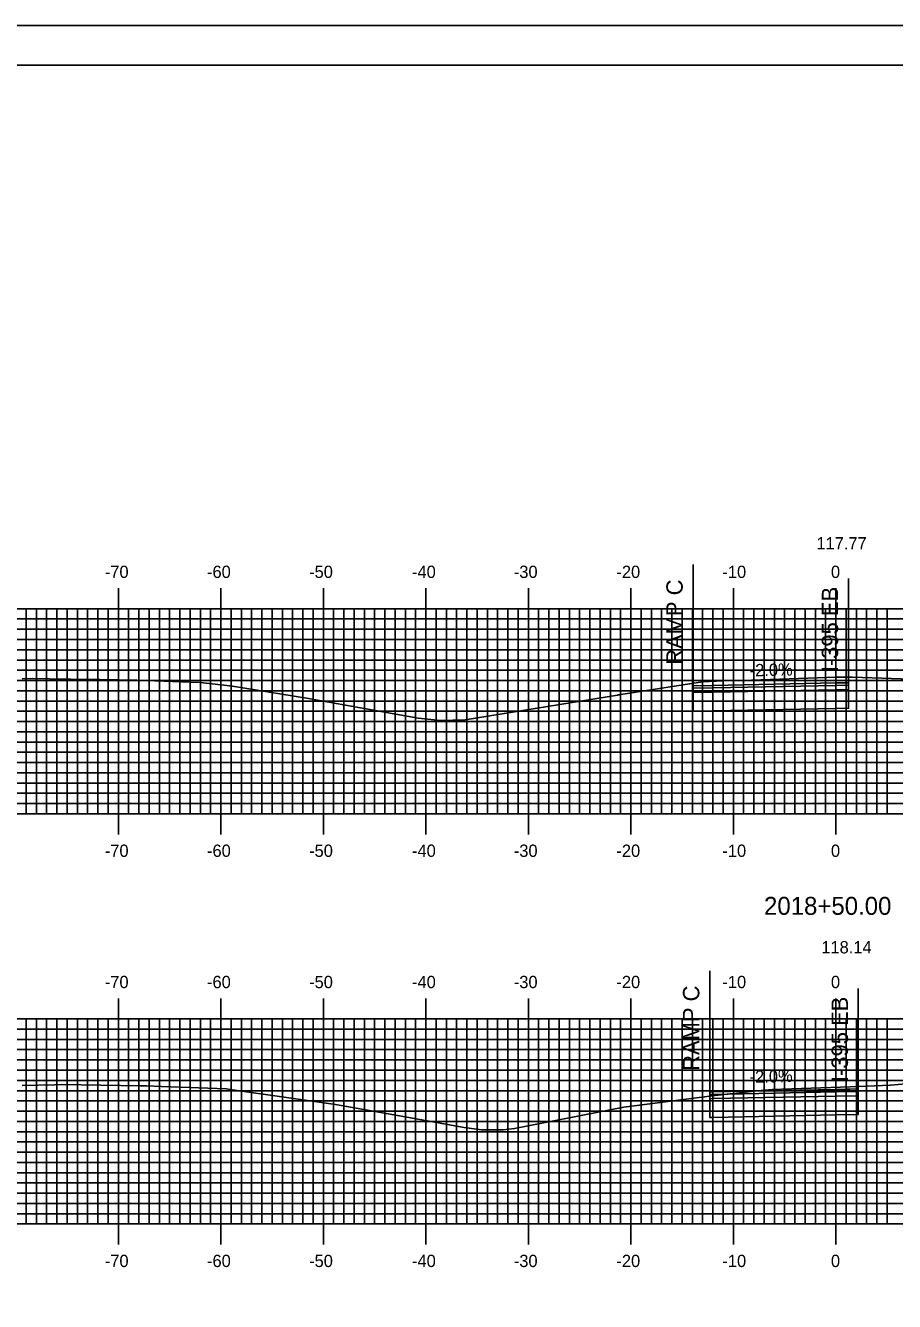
# Model space of a CAD drawing. Extents: x 855074 to 855418, y 366605 to 366825.
# Drawn here: x 855161 to 855245.8, y 366700.5 to 366824.9 of the extents above; entities that cross this region are included whole.
import ezdxf

# ---------------------------------------------------------------- set-up
doc = ezdxf.new("R2010")
doc.units = 0
for name, color, linetype in [('ANNOTATION', 7, 'Continuous'), ('BORDER', 7, 'Continuous'), ('D_Roadway_Centerline', 7, 'Continuous'), ('D_Roadway_Centerline_Text', 7, 'Continuous'), ('D_Roadway_Edge_Shoulder', 7, 'Continuous'), ('D_Roadway_Edge_TW', 7, 'Continuous'), ('D_Roadway_Pavement', 7, 'Continuous'), ('D_Roadway_SubGrade', 7, 'Continuous'), ('H_V ANNOTATION', 7, 'Continuous'), ('M_Roadway_Centerline', 7, 'Continuous'), ('MAJOR', 7, 'Continuous'), ('MINOR', 7, 'Continuous'), ('PLOT BOUNDARY', 7, 'Continuous'), ('S_Roadway_Centerline', 7, 'Continuous')]:
    doc.layers.add(name, color=color, linetype=linetype)

msp = doc.modelspace()

# ---------------------------------------------------------------- linework, layer by layer
at = {"layer": 'BORDER'}
msp.add_lwpolyline([(855090.47, 366611.06), (855410.47, 366611.06), (855410.47, 366821.06), (855090.47, 366821.06)], close=True, dxfattribs=at)
at = {"layer": 'D_Roadway_Centerline'}
for points in [[(855226.14, 366760.55), (855228.07, 366760.59), (855240.07, 366760.83), (855240.07, 366760.83), (855240.63, 366760.84), (855241.31, 366760.85)], [(855227.76, 366720.95), (855227.8, 366720.95), (855228.07, 366720.95), (855240.07, 366721.19), (855240.07, 366721.19), (855241.44, 366721.22), (855242.25, 366721.24)]]:
    msp.add_lwpolyline(points, dxfattribs=at)
at = {"layer": 'D_Roadway_Edge_Shoulder'}
for points in [[(855240.07, 366760.83), (855241.31, 366760.85), (855241.31, 366760.6), (855240.07, 366760.58)], [(855240.07, 366721.19), (855242.25, 366721.24), (855242.25, 366720.99), (855240.07, 366720.94)]]:
    msp.add_lwpolyline(points, close=True, dxfattribs=at)
at = {"layer": 'D_Roadway_Edge_TW'}
for points in [[(855228.07, 366760.59), (855226.14, 366760.55), (855226.14, 366760.3), (855228.07, 366760.34)], [(855240.07, 366760.83), (855228.07, 366760.59), (855228.07, 366760.34), (855240.07, 366760.58)], [(855228.07, 366720.95), (855227.76, 366720.95), (855227.76, 366720.7), (855228.07, 366720.7)], [(855240.07, 366721.19), (855228.07, 366720.95), (855228.07, 366720.7), (855240.07, 366720.94)]]:
    msp.add_lwpolyline(points, close=True, dxfattribs=at)
for points in [[(855228.07, 366760.59), (855228.07, 366760.34)], [(855228.07, 366720.95), (855228.07, 366720.7)]]:
    msp.add_lwpolyline(points, dxfattribs=at)
at = {"layer": 'D_Roadway_Pavement'}
for points in [[(855228.07, 366760.34), (855226.14, 366760.3), (855226.14, 366759.88), (855228.07, 366759.92)], [(855240.07, 366760.58), (855228.07, 366760.34), (855228.07, 366759.92), (855240.07, 366760.16)], [(855240.07, 366760.58), (855241.31, 366760.6), (855241.31, 366760.19), (855240.07, 366760.16)], [(855228.07, 366720.7), (855227.76, 366720.7), (855227.76, 366720.28), (855228.07, 366720.29)], [(855240.07, 366720.94), (855228.07, 366720.7), (855228.07, 366720.29), (855240.07, 366720.53)], [(855240.07, 366720.94), (855242.25, 366720.99), (855242.25, 366720.57), (855240.07, 366720.53)]]:
    msp.add_lwpolyline(points, close=True, dxfattribs=at)
for points in [[(855228.07, 366760.34), (855228.07, 366759.92)], [(855228.07, 366760.34), (855228.07, 366759.92)], [(855228.07, 366720.7), (855228.07, 366720.29)], [(855228.07, 366720.7), (855228.07, 366720.29)]]:
    msp.add_lwpolyline(points, dxfattribs=at)
at = {"layer": 'D_Roadway_SubGrade'}
for p, q in [((855226.14, 366772.36), (855226.14, 366758.05)), ((855241.31, 366771), (855241.31, 366758.35)), ((855227.76, 366732.75), (855227.76, 366718.45)), ((855242.25, 366731.02), (855242.25, 366718.74))]:
    msp.add_line(p, q, dxfattribs=at)
for points in [[(855240.07, 366760.16), (855241.31, 366760.19), (855241.31, 366760.6), (855241.31, 366760.85), (855241.31, 366758.35), (855240.07, 366758.33)], [(855228.07, 366759.92), (855226.14, 366759.88), (855226.14, 366758.05), (855228.07, 366758.09)], [(855240.07, 366760.16), (855228.07, 366759.92), (855228.07, 366758.09), (855240.07, 366758.33)], [(855240.07, 366720.53), (855228.07, 366720.29), (855228.07, 366718.45), (855240.07, 366718.69)], [(855240.07, 366720.53), (855242.25, 366720.57), (855242.25, 366720.99), (855242.25, 366721.24), (855242.25, 366718.74), (855240.07, 366718.69)], [(855228.07, 366720.29), (855227.76, 366720.28), (855227.76, 366718.45), (855228.07, 366718.45)]]:
    msp.add_lwpolyline(points, close=True, dxfattribs=at)
for points in [[(855228.07, 366759.92), (855228.07, 366758.09)], [(855228.07, 366720.29), (855228.07, 366718.45)]]:
    msp.add_lwpolyline(points, dxfattribs=at)
at = {"layer": 'MAJOR'}
for p, q in [((855170.07, 366770.06), (855170.07, 366768.06)), ((855180.07, 366770.06), (855180.07, 366768.06)), ((855190.07, 366770.06), (855190.07, 366768.06)), ((855200.07, 366770.06), (855200.07, 366768.06)), ((855210.07, 366770.06), (855210.07, 366768.06)), ((855220.07, 366770.06), (855220.07, 366768.06)), ((855230.07, 366770.06), (855230.07, 366768.06)), ((855240.07, 366770.06), (855240.07, 366768.06)), ((855100.07, 366768.06), (855380.07, 366768.06)), ((855100.07, 366768.06), (855380.07, 366768.06)), ((855170.07, 366748.06), (855170.07, 366768.06)), ((855180.07, 366748.06), (855180.07, 366768.06)), ((855190.07, 366748.06), (855190.07, 366768.06)), ((855200.07, 366748.06), (855200.07, 366768.06)), ((855210.07, 366748.06), (855210.07, 366768.06)), ((855220.07, 366748.06), (855220.07, 366768.06)), ((855230.07, 366748.06), (855230.07, 366768.06)), ((855240.07, 366748.06), (855240.07, 366768.06)), ((855100.07, 366763.06), (855380.07, 366763.06)), ((855100.07, 366758.06), (855380.07, 366758.06)), ((855100.07, 366753.06), (855380.07, 366753.06)), ((855100.07, 366748.06), (855380.07, 366748.06)), ((855100.07, 366748.06), (855380.07, 366748.06)), ((855170.07, 366746.05), (855170.07, 366748.06)), ((855180.07, 366746.05), (855180.07, 366748.06)), ((855190.07, 366746.05), (855190.07, 366748.06)), ((855200.07, 366746.05), (855200.07, 366748.06)), ((855210.07, 366746.05), (855210.07, 366748.06)), ((855220.07, 366746.05), (855220.07, 366748.06)), ((855230.07, 366746.05), (855230.07, 366748.06)), ((855240.07, 366746.05), (855240.07, 366748.06)), ((855170.07, 366730.06), (855170.07, 366728.06)), ((855180.07, 366730.06), (855180.07, 366728.06)), ((855190.07, 366730.06), (855190.07, 366728.06)), ((855200.07, 366730.06), (855200.07, 366728.06)), ((855210.07, 366730.06), (855210.07, 366728.06)), ((855220.07, 366730.06), (855220.07, 366728.06)), ((855230.07, 366730.06), (855230.07, 366728.06)), ((855240.07, 366730.06), (855240.07, 366728.06)), ((855100.07, 366728.06), (855380.07, 366728.06)), ((855100.07, 366728.06), (855380.07, 366728.06)), ((855170.07, 366708.06), (855170.07, 366728.06)), ((855180.07, 366708.06), (855180.07, 366728.06)), ((855190.07, 366708.06), (855190.07, 366728.06)), ((855200.07, 366708.06), (855200.07, 366728.06)), ((855210.07, 366708.06), (855210.07, 366728.06)), ((855220.07, 366708.06), (855220.07, 366728.06)), ((855230.07, 366708.06), (855230.07, 366728.06)), ((855240.07, 366708.06), (855240.07, 366728.06)), ((855100.07, 366723.06), (855380.07, 366723.06)), ((855100.07, 366718.06), (855380.07, 366718.06)), ((855100.07, 366713.06), (855380.07, 366713.06)), ((855100.07, 366708.06), (855380.07, 366708.06)), ((855100.07, 366708.06), (855380.07, 366708.06)), ((855170.07, 366706.05), (855170.07, 366708.06)), ((855180.07, 366706.05), (855180.07, 366708.06)), ((855190.07, 366706.05), (855190.07, 366708.06)), ((855200.07, 366706.05), (855200.07, 366708.06)), ((855210.07, 366706.05), (855210.07, 366708.06)), ((855220.07, 366706.05), (855220.07, 366708.06)), ((855230.07, 366706.05), (855230.07, 366708.06)), ((855240.07, 366706.05), (855240.07, 366708.06))]:
    msp.add_line(p, q, dxfattribs=at)
at = {"layer": 'MINOR'}
for p, q in [((855161.07, 366748.06), (855161.07, 366768.06)), ((855162.07, 366748.06), (855162.07, 366768.06)), ((855163.07, 366748.06), (855163.07, 366768.06)), ((855164.07, 366748.06), (855164.07, 366768.06)), ((855165.07, 366748.06), (855165.07, 366768.06)), ((855166.07, 366748.06), (855166.07, 366768.06)), ((855167.07, 366748.06), (855167.07, 366768.06)), ((855168.07, 366748.06), (855168.07, 366768.06)), ((855169.07, 366748.06), (855169.07, 366768.06)), ((855171.07, 366748.06), (855171.07, 366768.06)), ((855172.07, 366748.06), (855172.07, 366768.06)), ((855173.07, 366748.06), (855173.07, 366768.06)), ((855174.07, 366748.06), (855174.07, 366768.06)), ((855175.07, 366748.06), (855175.07, 366768.06)), ((855176.07, 366748.06), (855176.07, 366768.06)), ((855177.07, 366748.06), (855177.07, 366768.06)), ((855178.07, 366748.06), (855178.07, 366768.06)), ((855179.07, 366748.06), (855179.07, 366768.06)), ((855181.07, 366748.06), (855181.07, 366768.06)), ((855182.07, 366748.06), (855182.07, 366768.06)), ((855183.07, 366748.06), (855183.07, 366768.06)), ((855184.07, 366748.06), (855184.07, 366768.06)), ((855185.07, 366748.06), (855185.07, 366768.06)), ((855186.07, 366748.06), (855186.07, 366768.06)), ((855187.07, 366748.06), (855187.07, 366768.06)), ((855188.07, 366748.06), (855188.07, 366768.06)), ((855189.07, 366748.06), (855189.07, 366768.06)), ((855191.07, 366748.06), (855191.07, 366768.06)), ((855192.07, 366748.06), (855192.07, 366768.06)), ((855193.07, 366748.06), (855193.07, 366768.06)), ((855194.07, 366748.06), (855194.07, 366768.06)), ((855195.07, 366748.06), (855195.07, 366768.06)), ((855196.07, 366748.06), (855196.07, 366768.06)), ((855197.07, 366748.06), (855197.07, 366768.06)), ((855198.07, 366748.06), (855198.07, 366768.06)), ((855199.07, 366748.06), (855199.07, 366768.06)), ((855201.07, 366748.06), (855201.07, 366768.06)), ((855202.07, 366748.06), (855202.07, 366768.06)), ((855203.07, 366748.06), (855203.07, 366768.06)), ((855204.07, 366748.06), (855204.07, 366768.06)), ((855205.07, 366748.06), (855205.07, 366768.06)), ((855206.07, 366748.06), (855206.07, 366768.06)), ((855207.07, 366748.06), (855207.07, 366768.06)), ((855208.07, 366748.06), (855208.07, 366768.06)), ((855209.07, 366748.06), (855209.07, 366768.06)), ((855211.07, 366748.06), (855211.07, 366768.06)), ((855212.07, 366748.06), (855212.07, 366768.06)), ((855213.07, 366748.06), (855213.07, 366768.06)), ((855214.07, 366748.06), (855214.07, 366768.06)), ((855215.07, 366748.06), (855215.07, 366768.06)), ((855216.07, 366748.06), (855216.07, 366768.06)), ((855217.07, 366748.06), (855217.07, 366768.06)), ((855218.07, 366748.06), (855218.07, 366768.06)), ((855219.07, 366748.06), (855219.07, 366768.06)), ((855221.07, 366748.06), (855221.07, 366768.06)), ((855222.07, 366748.06), (855222.07, 366768.06)), ((855223.07, 366748.06), (855223.07, 366768.06)), ((855224.07, 366748.06), (855224.07, 366768.06)), ((855225.07, 366748.06), (855225.07, 366768.06)), ((855226.07, 366748.06), (855226.07, 366768.06)), ((855227.07, 366748.06), (855227.07, 366768.06)), ((855228.07, 366748.06), (855228.07, 366768.06)), ((855229.07, 366748.06), (855229.07, 366768.06)), ((855231.07, 366748.06), (855231.07, 366768.06)), ((855232.07, 366748.06), (855232.07, 366768.06)), ((855233.07, 366748.06), (855233.07, 366768.06)), ((855234.07, 366748.06), (855234.07, 366768.06)), ((855235.07, 366748.06), (855235.07, 366768.06)), ((855236.07, 366748.06), (855236.07, 366768.06)), ((855237.07, 366748.06), (855237.07, 366768.06)), ((855238.07, 366748.06), (855238.07, 366768.06)), ((855239.07, 366748.06), (855239.07, 366768.06)), ((855241.07, 366748.06), (855241.07, 366768.06)), ((855242.07, 366748.06), (855242.07, 366768.06)), ((855243.07, 366748.06), (855243.07, 366768.06)), ((855244.07, 366748.06), (855244.07, 366768.06)), ((855245.07, 366748.06), (855245.07, 366768.06)), ((855100.07, 366767.06), (855380.07, 366767.06)), ((855100.07, 366766.06), (855380.07, 366766.06)), ((855100.07, 366765.06), (855380.07, 366765.06)), ((855100.07, 366764.06), (855380.07, 366764.06)), ((855100.07, 366762.06), (855380.07, 366762.06)), ((855100.07, 366761.06), (855380.07, 366761.06)), ((855100.07, 366760.06), (855380.07, 366760.06)), ((855100.07, 366759.06), (855380.07, 366759.06)), ((855100.07, 366757.06), (855380.07, 366757.06)), ((855100.07, 366756.06), (855380.07, 366756.06)), ((855100.07, 366755.06), (855380.07, 366755.06)), ((855100.07, 366754.06), (855380.07, 366754.06)), ((855100.07, 366752.06), (855380.07, 366752.06)), ((855100.07, 366751.06), (855380.07, 366751.06)), ((855100.07, 366750.06), (855380.07, 366750.06)), ((855100.07, 366749.06), (855380.07, 366749.06)), ((855161.07, 366708.06), (855161.07, 366728.06)), ((855162.07, 366708.06), (855162.07, 366728.06)), ((855163.07, 366708.06), (855163.07, 366728.06)), ((855164.07, 366708.06), (855164.07, 366728.06)), ((855165.07, 366708.06), (855165.07, 366728.06)), ((855166.07, 366708.06), (855166.07, 366728.06)), ((855167.07, 366708.06), (855167.07, 366728.06)), ((855168.07, 366708.06), (855168.07, 366728.06)), ((855169.07, 366708.06), (855169.07, 366728.06)), ((855171.07, 366708.06), (855171.07, 366728.06)), ((855172.07, 366708.06), (855172.07, 366728.06)), ((855173.07, 366708.06), (855173.07, 366728.06)), ((855174.07, 366708.06), (855174.07, 366728.06)), ((855175.07, 366708.06), (855175.07, 366728.06)), ((855176.07, 366708.06), (855176.07, 366728.06)), ((855177.07, 366708.06), (855177.07, 366728.06)), ((855178.07, 366708.06), (855178.07, 366728.06)), ((855179.07, 366708.06), (855179.07, 366728.06)), ((855181.07, 366708.06), (855181.07, 366728.06)), ((855182.07, 366708.06), (855182.07, 366728.06)), ((855183.07, 366708.06), (855183.07, 366728.06)), ((855184.07, 366708.06), (855184.07, 366728.06)), ((855185.07, 366708.06), (855185.07, 366728.06)), ((855186.07, 366708.06), (855186.07, 366728.06)), ((855187.07, 366708.06), (855187.07, 366728.06)), ((855188.07, 366708.06), (855188.07, 366728.06)), ((855189.07, 366708.06), (855189.07, 366728.06)), ((855191.07, 366708.06), (855191.07, 366728.06)), ((855192.07, 366708.06), (855192.07, 366728.06)), ((855193.07, 366708.06), (855193.07, 366728.06)), ((855194.07, 366708.06), (855194.07, 366728.06)), ((855195.07, 366708.06), (855195.07, 366728.06)), ((855196.07, 366708.06), (855196.07, 366728.06)), ((855197.07, 366708.06), (855197.07, 366728.06)), ((855198.07, 366708.06), (855198.07, 366728.06)), ((855199.07, 366708.06), (855199.07, 366728.06)), ((855201.07, 366708.06), (855201.07, 366728.06)), ((855202.07, 366708.06), (855202.07, 366728.06)), ((855203.07, 366708.06), (855203.07, 366728.06)), ((855204.07, 366708.06), (855204.07, 366728.06)), ((855205.07, 366708.06), (855205.07, 366728.06)), ((855206.07, 366708.06), (855206.07, 366728.06)), ((855207.07, 366708.06), (855207.07, 366728.06)), ((855208.07, 366708.06), (855208.07, 366728.06)), ((855209.07, 366708.06), (855209.07, 366728.06)), ((855211.07, 366708.06), (855211.07, 366728.06)), ((855212.07, 366708.06), (855212.07, 366728.06)), ((855213.07, 366708.06), (855213.07, 366728.06)), ((855214.07, 366708.06), (855214.07, 366728.06)), ((855215.07, 366708.06), (855215.07, 366728.06)), ((855216.07, 366708.06), (855216.07, 366728.06)), ((855217.07, 366708.06), (855217.07, 366728.06)), ((855218.07, 366708.06), (855218.07, 366728.06)), ((855219.07, 366708.06), (855219.07, 366728.06)), ((855221.07, 366708.06), (855221.07, 366728.06)), ((855222.07, 366708.06), (855222.07, 366728.06)), ((855223.07, 366708.06), (855223.07, 366728.06)), ((855224.07, 366708.06), (855224.07, 366728.06)), ((855225.07, 366708.06), (855225.07, 366728.06)), ((855226.07, 366708.06), (855226.07, 366728.06)), ((855227.07, 366708.06), (855227.07, 366728.06)), ((855228.07, 366708.06), (855228.07, 366728.06)), ((855229.07, 366708.06), (855229.07, 366728.06)), ((855231.07, 366708.06), (855231.07, 366728.06)), ((855232.07, 366708.06), (855232.07, 366728.06)), ((855233.07, 366708.06), (855233.07, 366728.06)), ((855234.07, 366708.06), (855234.07, 366728.06)), ((855235.07, 366708.06), (855235.07, 366728.06)), ((855236.07, 366708.06), (855236.07, 366728.06)), ((855237.07, 366708.06), (855237.07, 366728.06)), ((855238.07, 366708.06), (855238.07, 366728.06)), ((855239.07, 366708.06), (855239.07, 366728.06)), ((855241.07, 366708.06), (855241.07, 366728.06)), ((855242.07, 366708.06), (855242.07, 366728.06)), ((855243.07, 366708.06), (855243.07, 366728.06)), ((855244.07, 366708.06), (855244.07, 366728.06)), ((855245.07, 366708.06), (855245.07, 366728.06)), ((855100.07, 366727.06), (855380.07, 366727.06)), ((855100.07, 366726.06), (855380.07, 366726.06)), ((855100.07, 366725.06), (855380.07, 366725.06)), ((855100.07, 366724.06), (855380.07, 366724.06)), ((855100.07, 366722.06), (855380.07, 366722.06)), ((855100.07, 366721.06), (855380.07, 366721.06)), ((855100.07, 366720.06), (855380.07, 366720.06)), ((855100.07, 366719.06), (855380.07, 366719.06)), ((855100.07, 366717.06), (855380.07, 366717.06)), ((855100.07, 366716.06), (855380.07, 366716.06)), ((855100.07, 366715.06), (855380.07, 366715.06)), ((855100.07, 366714.06), (855380.07, 366714.06)), ((855100.07, 366712.06), (855380.07, 366712.06)), ((855100.07, 366711.06), (855380.07, 366711.06)), ((855100.07, 366710.06), (855380.07, 366710.06)), ((855100.07, 366709.06), (855380.07, 366709.06))]:
    msp.add_line(p, q, dxfattribs=at)
at = {"layer": 'PLOT BOUNDARY'}
msp.add_lwpolyline([(855074.28, 366604.94), (855414.28, 366604.94), (855414.28, 366824.94), (855074.28, 366824.94)], close=True, dxfattribs=at)
at = {"layer": 'S_Roadway_Centerline'}
for points in [[(855160.68, 366761.23), (855161.73, 366761.27), (855163.34, 366761.22), (855167.54, 366761.17), (855168.26, 366761.16), (855171.91, 366761.1), (855176.24, 366760.94), (855177.98, 366760.87), (855178.07, 366760.87), (855181.19, 366760.5), (855188.41, 366759.34), (855199.33, 366757.38), (855201.51, 366757.15), (855203.91, 366757.22), (855218.75, 366759.64), (855218.87, 366759.65), (855219.03, 366759.68), (855219.08, 366759.69), (855227.05, 366760.92), (855229.04, 366761.02), (855231.84, 366761.11), (855240.11, 366761.39), (855241.7, 366761.4), (855249.3, 366761.12)], [(855160.69, 366721.56), (855163.83, 366721.62), (855164.49, 366721.65), (855172.24, 366721.54), (855172.83, 366721.52), (855174.28, 366721.47), (855180.62, 366721.23), (855180.97, 366721.18), (855186.93, 366720.32), (855191.25, 366719.72), (855197.49, 366718.62), (855203.8, 366717.47), (855205.51, 366717.24), (855207.61, 366717.23), (855208.72, 366717.37), (855219.37, 366719.44), (855228.01, 366720.57), (855232.41, 366721.05), (855233.86, 366721.18), (855241.47, 366721.44), (855245.4, 366721.61), (855246.88, 366721.73)]]:
    msp.add_lwpolyline(points, dxfattribs=at)

# ---------------------------------------------------------------- texts
at = {"layer": 'ANNOTATION'}
for s, height, rotation, p in [('RAMP C', 1.6, 90, (855225.13, 366762.59)), ('I-395 EB', 1.6, 90, (855240.29, 366761.87)), ('-2.0%', 1.2, 1.1458, (855231.67, 366761.46)), ('RAMP C', 1.6, 90, (855226.75, 366722.99)), ('I-395 EB', 1.6, 90, (855241.25, 366721.9)), ('-2.0%', 1.2, 1.1458, (855231.67, 366721.82))]:
    msp.add_text(s, height=height, rotation=rotation, dxfattribs=at).set_placement(p)
at = {"layer": 'D_Roadway_Centerline_Text'}
for s, p in [('117.77', (855238.17, 366773.84)), ('118.14', (855238.65, 366734.45))]:
    msp.add_text(s, height=1.2, dxfattribs=at).set_placement(p)
at = {"layer": 'H_V ANNOTATION'}
for s, height, p in [('-70', 1.2, (855168.75, 366771.06)), ('-60', 1.2, (855178.72, 366771.06)), ('-50', 1.2, (855188.68, 366771.06)), ('-40', 1.2, (855198.72, 366771.06)), ('-30', 1.2, (855208.65, 366771.06)), ('-20', 1.2, (855218.66, 366771.06)), ('-10', 1.2, (855229, 366771.06)), ('0', 1.2, (855239.59, 366771.06)), ('-70', 1.2, (855168.75, 366743.86)), ('-60', 1.2, (855178.72, 366743.86)), ('-50', 1.2, (855188.68, 366743.86)), ('-40', 1.2, (855198.72, 366743.86)), ('-30', 1.2, (855208.65, 366743.86)), ('-20', 1.2, (855218.66, 366743.86)), ('-10', 1.2, (855229, 366743.86)), ('0', 1.2, (855239.59, 366743.86)), ('2018+50.00', 1.75, (855233.06, 366738.21)), ('-70', 1.2, (855168.75, 366731.06)), ('-60', 1.2, (855178.72, 366731.06)), ('-50', 1.2, (855188.68, 366731.06)), ('-40', 1.2, (855198.72, 366731.06)), ('-30', 1.2, (855208.65, 366731.06)), ('-20', 1.2, (855218.66, 366731.06)), ('-10', 1.2, (855229, 366731.06)), ('0', 1.2, (855239.59, 366731.06)), ('-70', 1.2, (855168.75, 366703.86)), ('-60', 1.2, (855178.72, 366703.86)), ('-50', 1.2, (855188.68, 366703.86)), ('-40', 1.2, (855198.72, 366703.86)), ('-30', 1.2, (855208.65, 366703.86)), ('-20', 1.2, (855218.66, 366703.86)), ('-10', 1.2, (855229, 366703.86)), ('0', 1.2, (855239.59, 366703.86))]:
    msp.add_text(s, height=height, dxfattribs=at).set_placement(p)
at = {"layer": 'M_Roadway_Centerline'}
for s, p in [('C', (855161.72, 366761.27)), ('L', (855161.73, 366761.26)), ('C', (855240.1, 366761.39)), ('L', (855240.11, 366761.38)), ('C', (855164.49, 366721.65)), ('L', (855164.49, 366721.64))]:
    msp.add_text(s, height=0.0146, dxfattribs=at).set_placement(p)

doc.saveas('drawing.dxf')
